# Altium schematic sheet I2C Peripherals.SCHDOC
size A4; Revision: B.2
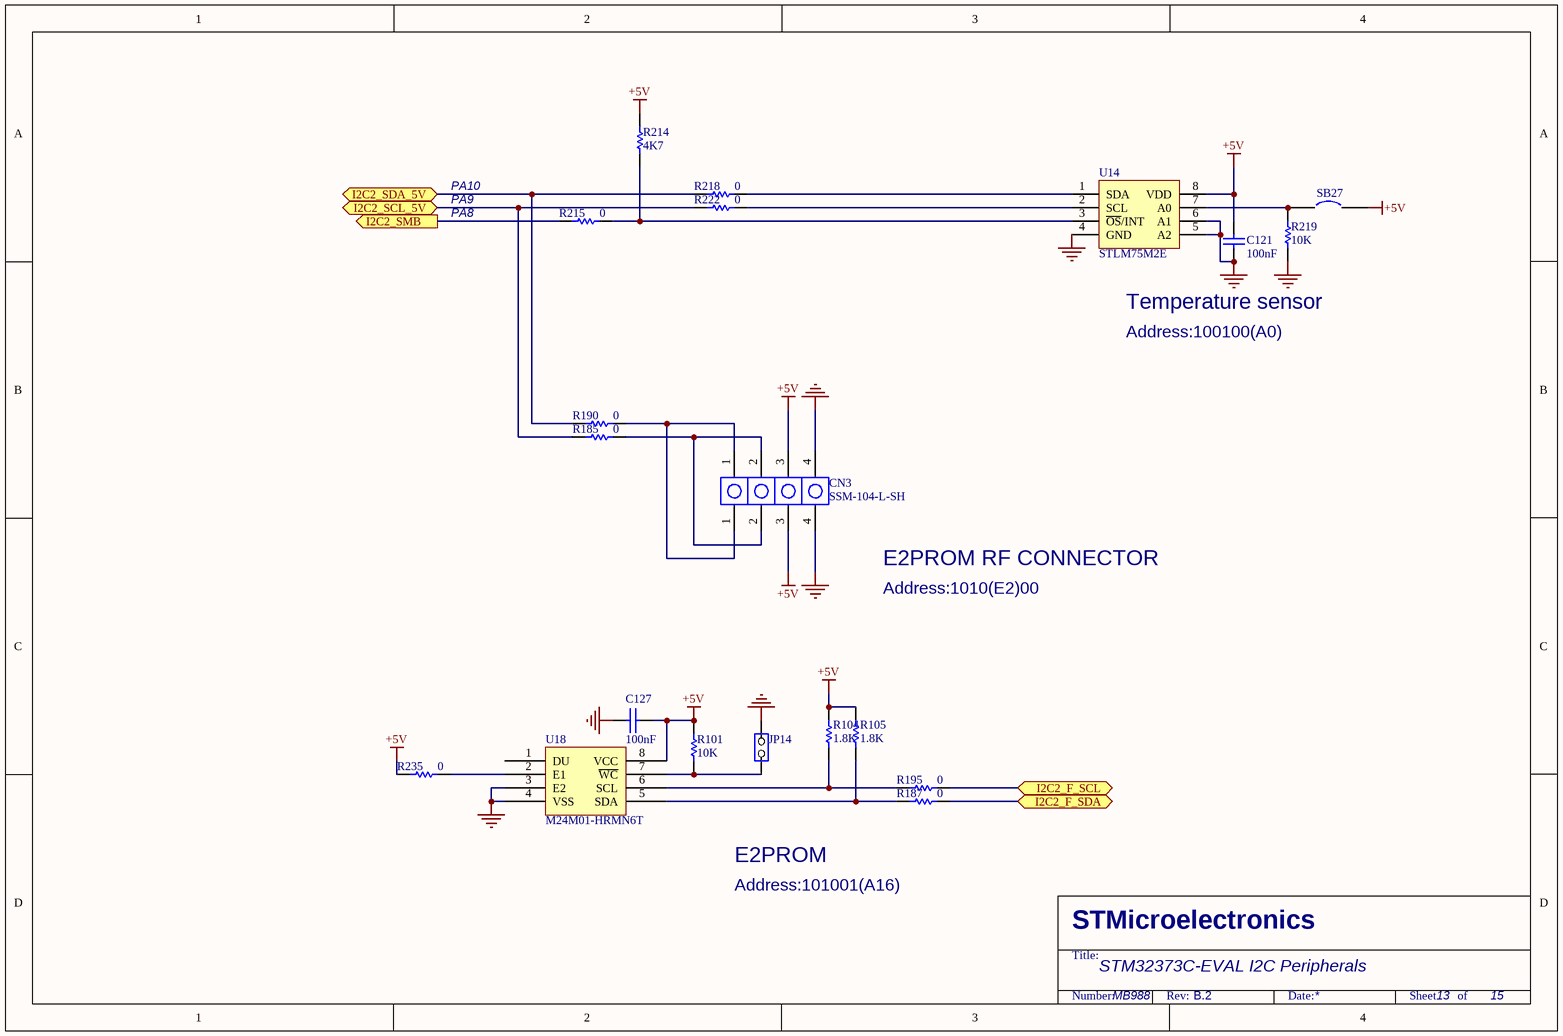
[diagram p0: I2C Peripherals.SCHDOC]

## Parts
C121  100nF  [0603C]
C127  100nF  [0603C]
CN3  SSM-104-L-SH  [SSM-104-L-SH]
JP14  (no value)  [SIP2]
R101  10K  [0603R]
R104  1.8K  [0603R]
R105  1.8K  [0603R]
R185  0  [0603R]
R187  0  [0603R]
R190  0  [0603R]
R195  0  [0603R]
R214  4K7  [0603R]
R215  0  [0603R]
R218  0  [0603R]
R219  10K  [0603R]
R222  0  [0603R]
R235  0  [0603R]
SB27  (no value)  [JP2_SMD]
U14  STLM75M2E  [SO8]
U18  M24M01-HRMN6T  [SO8]

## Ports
I2C2_F_SCL (bidir), I2C2_F_SDA (bidir), I2C2_SCL_5V (bidir), I2C2_SDA_5V (bidir), I2C2_SMB (out)

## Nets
+5V: C121.2 C127.2 CN3.3 R101.1 R104.2 R105.2 R214.2 R235.1 SB27.2 U14.8(VDD) U18.8(VCC)
GND: C121.1 C127.1 CN3.4 JP14.2(NO) R219.1 U14.4(GND) U14.5(A2) U14.6(A1) U18.3(E2) U18.4(VSS)
I2C2_F_SCL: R195.2 ; port I2C2_F_SCL
I2C2_F_SDA: R187.2 ; port I2C2_F_SDA
I2C2_SCL_5V: R185.1 R222.1 ; port I2C2_SCL_5V
I2C2_SDA_5V: R190.1 R218.1 ; port I2C2_SDA_5V
I2C2_SMB: R215.2 ; port I2C2_SMB
NetCN3_1: CN3.1 R190.2
NetCN3_2: CN3.2 R185.2
NetJP14_1: JP14.1(COMMON) R101.2 U18.7(~{WC})
NetR104_1: R104.1 R195.1 U18.6(SCL)
NetR105_1: R105.1 R187.1 U18.5(SDA)
NetR214_1: R214.1 R215.1 U14.3(~{OS}/INT)
NetR218_2: R218.2 U14.1(SDA)
NetR219_2: R219.2 SB27.1 U14.7(A0)
NetR222_2: R222.2 U14.2(SCL)
NetR235_2: R235.2 U18.2(E1)

Not connected (* = marked no-connect by the designer): U18 1(DU)

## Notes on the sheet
- PA10
- PA9
- PA8
- Temperature sensor
- Address:100100(A0)
- E2PROM RF CONNECTOR
- Address:1010(E2)00
- Address:101001(A16)
- E2PROM
- STM32373C-EVAL I2C Peripherals
- MB988
- 13
- 15

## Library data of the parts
C121 = cap: Capacitor; Value: 100pF
C127 = CAP: Capacitor
JP14 = JP2
R101 = res1: Resistor; Value: 1K
R104 R105 R185 R187 R190 R195 R214 R215 R218 R219 R222 R235 = Res1: Resistor; Value: 1K
SB27 = Circuit Breaker
U14 = STLM75DW2F
U18 = M24M01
